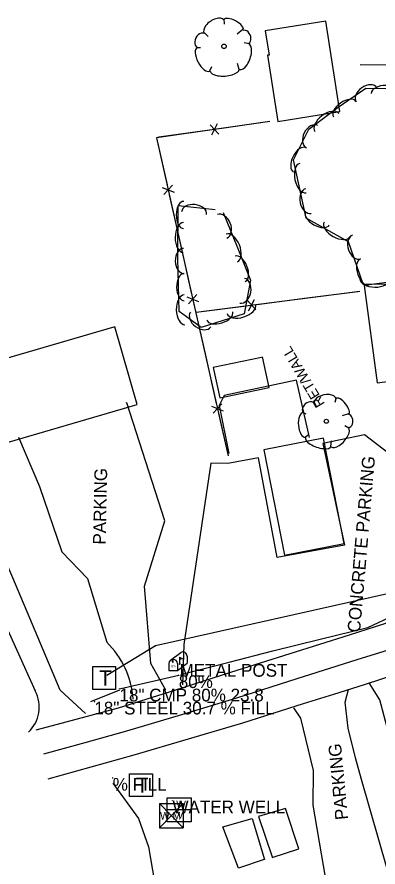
# Model space of a CAD drawing. Extents: x 954793 to 988390, y 1867850 to 1924428.
# Drawn here: x 960736.3 to 960878, y 1902924.1 to 1903257.7 of the extents above; entities that cross this region are included whole.
import ezdxf

# ---------------------------------------------------------------- set-up
doc = ezdxf.new("R2010")
doc.units = 0
for name, color, linetype in [('S_BUILDING', 7, 'Continuous'), ('S_CROSS_DRAIN_ANNOT', 7, 'Continuous'), ('S_DITCHLINE', 7, 'Continuous'), ('S_DRG_PT_SYM', 7, 'Continuous'), ('S_DRIVEWAY', 7, 'Continuous'), ('S_EDGE_PAVEMENT', 7, 'Continuous'), ('S_FENCE', 7, 'Continuous'), ('S_FIBER_OPTIC_CABLE', 7, 'Continuous'), ('S_LANDSCAPING', 7, 'Continuous'), ('S_MAILBOX', 7, 'Continuous'), ('S_MAILBOX_ANNOT', 7, 'Continuous'), ('S_MISC_STRUCTURES', 7, 'Continuous'), ('S_MISC_STRUCTURES_ANNOT', 7, 'Continuous'), ('S_MSC_PT_SYM', 7, 'Continuous'), ('S_PARKING', 7, 'Continuous'), ('S_PARKING_ANNOT', 7, 'Continuous'), ('S_PAVEMENT_CROWN', 7, 'Continuous'), ('S_SIDE_DRAIN', 7, 'Continuous'), ('S_SIDE_DRAIN_ANNOT', 7, 'Continuous'), ('S_STREAM', 7, 'Continuous'), ('S_TELEPHONE_UTILITIES', 7, 'Continuous'), ('S_TRAILS', 7, 'Continuous'), ('S_TREE', 7, 'Continuous'), ('S_UTL_PT_SYM', 7, 'Continuous'), ('S_WALL', 7, 'Continuous'), ('S_WATER_UTILITIES', 7, 'Continuous')]:
    doc.layers.add(name, color=color, linetype=linetype)

msp = doc.modelspace()

# ---------------------------------------------------------------- linework, layer by layer
at = {"layer": 'S_BUILDING'}
for points in [[(960834.61, 1903242.7), (960838.71, 1903216.78), (960863.1, 1903220.64), (960857.49, 1903256.12), (960833.79, 1903252.37), (960835.3, 1903242.81)], [(960877.68, 1903114.07), (960925.19, 1903120.38), (960920.11, 1903158.65), (960872.6, 1903152.35)], [(960774.65, 1903136.12), (960718.08, 1903119.69), (960726.95, 1903089.15), (960783.52, 1903105.59)], [(960833.27, 1903087.89), (960841.27, 1903046.54), (960864.71, 1903051.08), (960856.7, 1903092.42)]]:
    msp.add_lwpolyline(points, close=True, dxfattribs=at)
at = {"layer": 'S_DITCHLINE'}
for points in [[(960800.47, 1902999.33), (960802.59, 1903000.11), (960819.64, 1903004.51), (960836.7, 1903008.92), (960855.38, 1903013.49), (960874.05, 1903018.05), (960884.7, 1903022.99)], [(960776.57, 1902993.42), (960765.15, 1902988.91)]]:
    msp.add_lwpolyline(points, dxfattribs=at)
at = {"layer": 'S_DRG_PT_SYM'}
for points in [[(960799.81, 1902999.31), (960799.81, 1902999.36), (960799.81, 1902999.31), (960799.76, 1902999.31), (960799.81, 1902999.31), (960799.81, 1902999.26), (960799.81, 1902999.31), (960799.86, 1902999.31)], [(960776.54, 1902994.06), (960776.54, 1902994.11), (960776.54, 1902994.06), (960776.49, 1902994.06), (960776.54, 1902994.06), (960776.54, 1902994.01), (960776.54, 1902994.06), (960776.59, 1902994.06)], [(960766.67, 1902988.94), (960766.67, 1902988.99), (960766.67, 1902988.94), (960766.62, 1902988.94), (960766.67, 1902988.94), (960766.67, 1902988.89), (960766.67, 1902988.94), (960766.72, 1902988.94)], [(960773.89, 1902959.02), (960773.89, 1902959.07), (960773.89, 1902959.02), (960773.84, 1902959.02), (960773.89, 1902959.02), (960773.89, 1902958.97), (960773.89, 1902959.02), (960773.94, 1902959.02)]]:
    msp.add_lwpolyline(points, dxfattribs=at)
at = {"layer": 'S_DRIVEWAY'}
for points in [[(960627.8, 1903162.47), (960637.57, 1903151.53), (960671.53, 1903129.07), (960689.76, 1903108.9), (960708.88, 1903070.75), (960733.27, 1903015.83), (960743.43, 1902993.16)], [(960763.17, 1902984.34), (960753.29, 1902993.45), (960734.68, 1903037.63), (960723.37, 1903063.58), (960693.32, 1903128.57), (960665.42, 1903160.73)], [(960779.36, 1903106.25), (960779.01, 1903106.14)], [(960794.68, 1902993.53), (960788.88, 1903003.95), (960786.3, 1903034.36), (960794.37, 1903060.01), (960779.36, 1903106.25)], [(960736.88, 1903092.74), (960745.1, 1903073.43), (960753.85, 1903047.79), (960763.98, 1903037.28), (960771.58, 1903012.29)]]:
    msp.add_lwpolyline(points, dxfattribs=at)
for centre, major_axis, ratio, start_param, end_param in [((960748.47, 1902987.42), (-6.96, 34.03), 0.96654, 4.590182, 5.316814), ((960732.05, 1902986.83), (-1.94, 13.04), 0.986221, 3.728095, 5.068124)]:
    msp.add_ellipse(centre, major_axis=major_axis, ratio=ratio, start_param=start_param, end_param=end_param, dxfattribs=at)
at = {"layer": 'S_EDGE_PAVEMENT'}
for points in [[(960887.9, 1903021.9), (960866.73, 1903015.03), (960843.45, 1903007.71), (960820.17, 1903000.4), (960798.12, 1902993.38), (960776.07, 1902986.36), (960759.9, 1902982.08), (960743.74, 1902977.79)], [(960893.77, 1903002.48), (960872.54, 1902995.61), (960860.62, 1902991.84), (960848.7, 1902988.06), (960836.79, 1902984.29), (960824.87, 1902980.52), (960803.54, 1902974.23), (960782.22, 1902967.95), (960765.34, 1902963.25), (960748.46, 1902958.54)]]:
    msp.add_lwpolyline(points, dxfattribs=at)
at = {"layer": 'S_FENCE'}
for p, q in [((960815.52, 1903211.76), (960812.11, 1903215.42)), ((960814.95, 1903215.82), (960812.68, 1903211.36)), ((960793.32, 1903190.85), (960797.94, 1903188.95)), ((960797.32, 1903191.75), (960793.95, 1903188.05)), ((960802.97, 1903147.92), (960807.59, 1903146.01)), ((960806.96, 1903148.81), (960803.59, 1903145.12)), ((960826.73, 1903146.5), (960830.1, 1903142.8)), ((960827.25, 1903142.44), (960829.58, 1903146.87)), ((960812.67, 1903105), (960817.29, 1903103.1)), ((960816.66, 1903105.9), (960813.3, 1903102.2))]:
    msp.add_line(p, q, dxfattribs=at)
for points in [[(960835.59, 1903216.67), (960791.03, 1903210.37), (960806.37, 1903142.08), (960819.18, 1903085.5)], [(960835.59, 1903216.67), (960815.8, 1903213.87)], [(960792.04, 1903210.51), (960791.03, 1903210.37), (960795.19, 1903191.85)], [(960811.84, 1903213.31), (960792.04, 1903210.51)], [(960796.07, 1903187.95), (960800.46, 1903168.43)], [(960800.46, 1903168.43), (960804.84, 1903148.92)], [(960806.59, 1903141.86), (960870.94, 1903150.09)], [(960830.4, 1903144.91), (960850.24, 1903147.44)], [(960850.24, 1903147.44), (960870.08, 1903149.98)], [(960805.72, 1903145.01), (960806.37, 1903142.08), (960810.13, 1903125.51)], [(960806.59, 1903141.86), (960826.43, 1903144.4)], [(960810.13, 1903125.51), (960814.54, 1903106)], [(960815.42, 1903102.1), (960819.18, 1903085.5)]]:
    msp.add_lwpolyline(points, dxfattribs=at)
at = {"layer": 'S_FIBER_OPTIC_CABLE'}
for p, q in [((960882.88, 1903031.6), (960790.61, 1903010.88)), ((960790.61, 1903010.88), (960771.57, 1902999.25))]:
    msp.add_line(p, q, dxfattribs=at)
at = {"layer": 'S_MAILBOX'}
for p, q in [((960796.5, 1903005.19), (960800.64, 1903008.3)), ((960803.07, 1903006.82), (960803.07, 1903004.11)), ((960795.95, 1903003.92), (960795.95, 1903001.2)), ((960799.27, 1903001.2), (960803.07, 1903004.11)), ((960799.27, 1903003.92), (960799.27, 1903001.2)), ((960800.12, 1903006.48), (960800.12, 1903003.76)), ((960795.95, 1903001.2), (960799.27, 1903001.2))]:
    msp.add_line(p, q, dxfattribs=at)
for points in [[(960797.13, 1903005.03), (960797.35, 1903004.89), (960797.35, 1903004.5), (960797.66, 1903004.5), (960797.66, 1903004.86), (960797.47, 1903005.11), (960797.13, 1903005.06)], [(960800.12, 1903006.48), (960801.23, 1903005.81), (960800.12, 1903005.47)]]:
    msp.add_lwpolyline(points, dxfattribs=at)
for centre, end in [((960801.41, 1903006.82), 117.5718), ((960797.61, 1903003.92), 180)]:
    msp.add_arc(centre, 1.66, 0, end, dxfattribs=at)
msp.add_ellipse((960800.12, 1903003.76), major_axis=(0.145, 0.132), ratio=0.564646, dxfattribs=at)
at = {"layer": 'S_MISC_STRUCTURES'}
for points in [[(960832.28, 1903124.08), (960813.3, 1903120.15), (960815.9, 1903108.28), (960835.33, 1903112.35), (960832.73, 1903124.3)], [(960836.45, 1902927.83), (960846.93, 1902931.23), (960841.78, 1902947.05), (960831.16, 1902943.9), (960836.43, 1902928.02)], [(960833.32, 1902927.02), (960823.29, 1902923.6), (960817.07, 1902939.85), (960828.62, 1902943.09), (960833.42, 1902927.04)]]:
    msp.add_lwpolyline(points, dxfattribs=at)
at = {"layer": 'S_MSC_PT_SYM'}
msp.add_lwpolyline([(960797.34, 1902950.11), (960797.34, 1902950.16), (960797.34, 1902950.11), (960797.29, 1902950.11), (960797.34, 1902950.11), (960797.34, 1902950.06), (960797.34, 1902950.11), (960797.39, 1902950.11)], dxfattribs=at)
at = {"layer": 'S_PARKING'}
for points in [[(960906.03, 1903068.21), (960872.72, 1903093.69), (960856.43, 1903090.34), (960864.94, 1903050.39), (960838.39, 1903045.56), (960831.05, 1903084.68), (960819.11, 1903082.5), (960812.39, 1903082.56), (960801.79, 1903011.46), (960801.25, 1902995.56)], [(960919.92, 1903009.86), (960926.45, 1902989.46), (960930.89, 1902972.76), (960885.92, 1902962.66), (960878.81, 1902989.7), (960874.59, 1902996.3)], [(960844.9, 1902986.56), (960847.56, 1902982.43), (960852.59, 1902961.88), (960852.48, 1902948.34), (960859.8, 1902905.55), (960885.16, 1902911.08), (960871.58, 1902958.4), (960869.17, 1902966.96), (960866.26, 1902978.61), (960865.08, 1902988.81), (960866.44, 1902993.7)]]:
    msp.add_lwpolyline(points, dxfattribs=at)
at = {"layer": 'S_PAVEMENT_CROWN'}
msp.add_lwpolyline([(961019.69, 1903046.96), (961007.34, 1903044.6), (960994.99, 1903042.24), (960974, 1903036.42), (960953.01, 1903030.6), (960932.57, 1903024.55), (960912.14, 1903018.51), (960890.94, 1903011.98), (960869.75, 1903005.44), (960846.11, 1902997.87), (960822.48, 1902990.3), (960800.88, 1902983.82), (960779.29, 1902977.33), (960762.98, 1902972.84), (960746.67, 1902968.36)], dxfattribs=at)
msp.add_lwpolyline([(961019.69, 1903046.96), (961007.34, 1903044.6), (960994.99, 1903042.24), (960974, 1903036.42), (960953.01, 1903030.6), (960932.57, 1903024.55), (960912.14, 1903018.51), (960890.94, 1903011.98), (960869.75, 1903005.44), (960846.11, 1902997.87), (960822.48, 1902990.3), (960800.88, 1902983.82), (960779.29, 1902977.33), (960762.98, 1902972.84), (960746.67, 1902968.36)], dxfattribs=at)
at = {"layer": 'S_SIDE_DRAIN'}
msp.add_line((960776.54, 1902994.06), (960799.81, 1902999.31), dxfattribs=at)
at = {"layer": 'S_STREAM'}
msp.add_lwpolyline([(960773.91, 1902956.93), (960783.97, 1902943.12), (960787.87, 1902931.94), (960791.92, 1902908.29), (960814.05, 1902854.54), (960817.97, 1902843.21), (960822.68, 1902827.38), (960828.76, 1902815.68), (960831.74, 1902797.21), (960837.99, 1902777.54), (960836.45, 1902762.8), (960832.17, 1902750.04)], dxfattribs=at)
at = {"layer": 'S_TELEPHONE_UTILITIES'}
for points in [[(960766.01, 1902993.8), (960766.01, 1903002.8), (960775.01, 1903002.8), (960775.01, 1902993.8)], [(960780.46, 1902951.68), (960780.46, 1902960.68), (960789.46, 1902960.68), (960789.46, 1902951.68)]]:
    msp.add_lwpolyline(points, close=True, dxfattribs=at)
at = {"layer": 'S_TRAILS'}
msp.add_lwpolyline([(960950.64, 1903242.76), (960900.37, 1903238.74), (960871.01, 1903238.99)], dxfattribs=at)
at = {"layer": 'S_TREE'}
for p, q in [((960817.44, 1903257.02), (960817.69, 1903254.92)), ((960809.91, 1903251.49), (960811.34, 1903250.13)), ((960824.9, 1903252.82), (960822.74, 1903250.98)), ((960827.46, 1903247.27), (960825.53, 1903247.56)), ((960806.76, 1903245.82), (960808.35, 1903245.77)), ((960812.03, 1903236.65), (960812.85, 1903238.26)), ((960823.47, 1903237.15), (960822.81, 1903239.43)), ((960861.59, 1903108.31), (960861.04, 1903106.42)), ((960853.14, 1903106.32), (960853.86, 1903104.64)), ((960848.38, 1903102.63), (960849.72, 1903102)), ((960866.44, 1903102.01), (960863.92, 1903101.21)), ((960866.6, 1903096.33), (960865.06, 1903097.28)), ((960849.54, 1903092.87), (960850.83, 1903093.94)), ((960859.51, 1903089.13), (960859.78, 1903091.31))]:
    msp.add_line(p, q, dxfattribs=at)
for points in [[(960919.76, 1903187.59), (960924.83, 1903174.06), (960914.28, 1903160.71), (960899.68, 1903152.6), (960872.25, 1903152.84), (960866.43, 1903169.5), (960849.8, 1903178.75), (960844.87, 1903201.62), (960850.91, 1903213.65), (960862.35, 1903222.4), (960873.26, 1903229.86), (960892.61, 1903229.69), (960908.08, 1903219.74), (960916.64, 1903196.19)], [(960817.21, 1903181.05), (960822.71, 1903167.55), (960827.94, 1903154.49), (960825.44, 1903141.19), (960808.59, 1903135.9), (960799.98, 1903142.19), (960799.44, 1903163.03), (960799.62, 1903183.81), (960814.14, 1903182.16)]]:
    msp.add_lwpolyline(points, dxfattribs=at)
for centre, radius in [((960817.56, 1903246.23), 0.862), ((960857.76, 1903099.04), 0.801)]:
    msp.add_circle(centre, radius, dxfattribs=at)
for centre, major_axis, ratio, start_param, end_param in [((960813.61, 1903253.98), (3.84, 2.64), 0.529943, 0, 3.141593), ((960821.27, 1903254.61), (3.8, -2.06), 0.420543, 6.283185, 9.424777), ((960808.4, 1903248.56), (-1.34, -2.68), 0.711534, 3.141592, 6.283185), ((960826.22, 1903250.01), (1.1, -2.48), 0.646762, 0, 3.141593), ((960825.4, 1903242.27), (-1.79, -5.14), 0.471018, 0, 3.141593), ((960809.62, 1903241.21), (2.47, -4.68), 0.482994, 3.141593, 6.283185), ((960817.84, 1903236.88), (5.72, 0.37), 0.405113, 3.141593, 6.283186), ((960873.59, 1903227.2), (-4.09, -2.8), 0.685311, 3.141593, 6.283185), ((960881.27, 1903227.67), (-5.87, 0.05), 0.55008, 3.141593, 6.283185), ((960864.94, 1903221.6), (-4.41, -3.02), 0.540699, 3.141593, 6.283185), ((960857.94, 1903216.35), (-4.66, -3.57), 0.55008, 3.141593, 6.283185), ((960852.13, 1903210.76), (-2.22, -4.43), 0.685311, 3.141593, 6.283185), ((960847.27, 1903201.67), (-2.4, -4.78), 0.540699, 3.141593, 6.283185), ((960848.58, 1903194.5), (1.24, -5.74), 0.55008, 3.141593, 6.283185), ((960850.78, 1903185.5), (1.04, -4.84), 0.685311, 3.141593, 6.283185), ((960801.71, 1903180.02), (-0.05, -5.35), 0.540699, 3.141593, 6.283185), ((960805.84, 1903180.71), (-4.92, 0.56), 0.685311, 3.141593, 6.283185), ((960816.87, 1903175.56), (-1.87, 4.59), 0.685311, 3.141593, 6.283185), ((960854.25, 1903178.7), (4.67, -2.6), 0.540699, 3.141593, 6.283185), ((960801.63, 1903171.16), (-0.05, -5.87), 0.55008, 3.141593, 6.283185), ((960862, 1903174.4), (5.13, -2.85), 0.55008, 3.141593, 6.283185), ((960820.61, 1903167.09), (-2.22, 5.43), 0.55008, 3.141593, 6.283185), ((960869.67, 1903167.45), (1.63, -4.68), 0.685311, 3.141593, 6.283185), ((960801.85, 1903161.98), (0.13, -4.95), 0.685311, 3.141593, 6.283185), ((960823.91, 1903158.87), (-1.99, 4.96), 0.540699, 3.141593, 6.283185), ((960872.82, 1903157.64), (1.76, -5.05), 0.540699, 3.141593, 6.283185), ((960801.85, 1903151.67), (0.14, -5.34), 0.540699, 3.141593, 6.283185), ((960824.72, 1903150.28), (0.92, 4.87), 0.685311, 3.141593, 6.283185), ((960876.79, 1903154.92), (5.87, -0.05), 0.55008, 3.141593, 6.283185), ((960802.08, 1903142.81), (0.15, -5.87), 0.55008, 3.141593, 6.283185), ((960824.36, 1903143.08), (5.6, 1.76), 0.55008, 3.141593, 6.283185), ((960808.4, 1903138.99), (4, -2.92), 0.685311, 3.141593, 6.283185), ((960815.9, 1903140.42), (5.1, 1.6), 0.540699, 3.141593, 6.283185), ((960850.78, 1903104.36), (-2.12, -1.81), 0.711534, 3.141592, 6.283185), ((960857.21, 1903107.11), (4.24, 0.86), 0.529943, 0, 3.141593), ((960863.98, 1903104.85), (2.5, -3.15), 0.420543, 6.283185, 9.424777), ((960849.15, 1903097.64), (0.41, -4.9), 0.482994, 3.141593, 6.283185), ((960866.54, 1903099.12), (0.04, -2.52), 0.646762, 0, 3.141593), ((960863.02, 1903092.8), (-3.4, -3.74), 0.471018, 0, 3.141593), ((960854.6, 1903090.95), (5.03, -1.77), 0.405113, 3.141593, 6.283186)]:
    msp.add_ellipse(centre, major_axis=major_axis, ratio=ratio, start_param=start_param, end_param=end_param, dxfattribs=at)
at = {"layer": 'S_UTL_PT_SYM'}
for points in [[(960790.61, 1903010.88), (960790.61, 1903010.93), (960790.61, 1903010.88), (960790.56, 1903010.88), (960790.61, 1903010.88), (960790.61, 1903010.83), (960790.61, 1903010.88), (960790.66, 1903010.88)], [(960771.57, 1902999.25), (960771.57, 1902999.3), (960771.57, 1902999.25), (960771.52, 1902999.25), (960771.57, 1902999.25), (960771.57, 1902999.2), (960771.57, 1902999.25), (960771.62, 1902999.25)]]:
    msp.add_lwpolyline(points, dxfattribs=at)
at = {"layer": 'S_WALL'}
msp.add_lwpolyline([(960851.13, 1903092.67), (960846.05, 1903115.13), (960817.68, 1903109.14), (960815.71, 1903105.28), (960819.46, 1903086.43)], dxfattribs=at)
at = {"layer": 'S_WATER_UTILITIES'}
for p, q in [((960795.28, 1902951.27), (960804.69, 1902951.27)), ((960795.28, 1902941.85), (960795.28, 1902951.27)), ((960804.69, 1902951.27), (960804.69, 1902941.85)), ((960792.24, 1902948.93), (960801.58, 1902948.93)), ((960792.24, 1902948.93), (960792.24, 1902939.44)), ((960792.24, 1902948.93), (960801.58, 1902939.44)), ((960801.58, 1902948.93), (960792.24, 1902939.44)), ((960801.58, 1902948.93), (960801.58, 1902939.44)), ((960795.28, 1902946.58), (960804.69, 1902946.58)), ((960804.69, 1902941.85), (960795.28, 1902941.85)), ((960792.24, 1902939.44), (960801.58, 1902939.44))]:
    msp.add_line(p, q, dxfattribs=at)

# ---------------------------------------------------------------- texts
at = {"layer": 'S_CROSS_DRAIN_ANNOT'}
for s, p in [('18" STEEL 30.7 % FILL', (960766.67, 1902983.94)), ('% FILL', (960773.89, 1902954.02))]:
    msp.add_text(s, height=5, dxfattribs=at).set_placement(p)
at = {"layer": 'S_LANDSCAPING'}
msp.add_text('RET/WALL', height=4, rotation=120.7914, dxfattribs=at).set_placement((960857.29, 1903105.9))
at = {"layer": 'S_MAILBOX'}
msp.add_text('US', height=0.96, rotation=360, dxfattribs=at).set_placement((960796.71, 1903002.39))
at = {"layer": 'S_MAILBOX_ANNOT'}
msp.add_text('METAL POST', height=5, dxfattribs=at).set_placement((960800.12, 1902998.76))
at = {"layer": 'S_MISC_STRUCTURES_ANNOT'}
msp.add_text('WATER WELL', height=5, dxfattribs=at).set_placement((960797.34, 1902945.11))
at = {"layer": 'S_PARKING_ANNOT'}
for s, height, rotation, p in [('CONCRETE PARKING', 5.0004, 85.1266, (960870.99, 1903015.97)), ('PARKING', 5, 88.869, (960771.13, 1903050.58)), ('PARKING', 5, 95.4371, (960866.32, 1902942.79))]:
    msp.add_text(s, height=height, rotation=rotation, dxfattribs=at).set_placement(p)
at = {"layer": 'S_SIDE_DRAIN_ANNOT'}
for s, p in [('80%', (960799.81, 1902994.31)), ('18" CMP 80% 23.8', (960776.54, 1902989.06))]:
    msp.add_text(s, height=5, dxfattribs=at).set_placement(p)
at = {"layer": 'S_TELEPHONE_UTILITIES'}
for p in [(960768.57, 1902995.3), (960783.02, 1902953.18)]:
    msp.add_text('T', height=6, rotation=360, dxfattribs=at).set_placement(p)
at = {"layer": 'S_WATER_UTILITIES'}
for s, p in [('W', (960798.83, 1902947.11)), ('W M', (960792.44, 1902942.7)), ('V', (960799.06, 1902943.04))]:
    msp.add_text(s, height=3, rotation=360, dxfattribs=at).set_placement(p)

doc.saveas('drawing.dxf')
